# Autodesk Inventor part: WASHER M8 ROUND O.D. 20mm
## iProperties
Created: 2007-04
Part Number: WASHER M8 ROUND O.D. 20mm
Material: Steel
Document SubType Name: Modeling
Designer: Andy Moles
Density: 7.85 g/cm^3
Mass: 3.03105 g
Surface Area: 6.49132 cm^2
Volume: 0.386121 cm^3
Author: Andy Moles
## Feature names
1. Extrusion1
